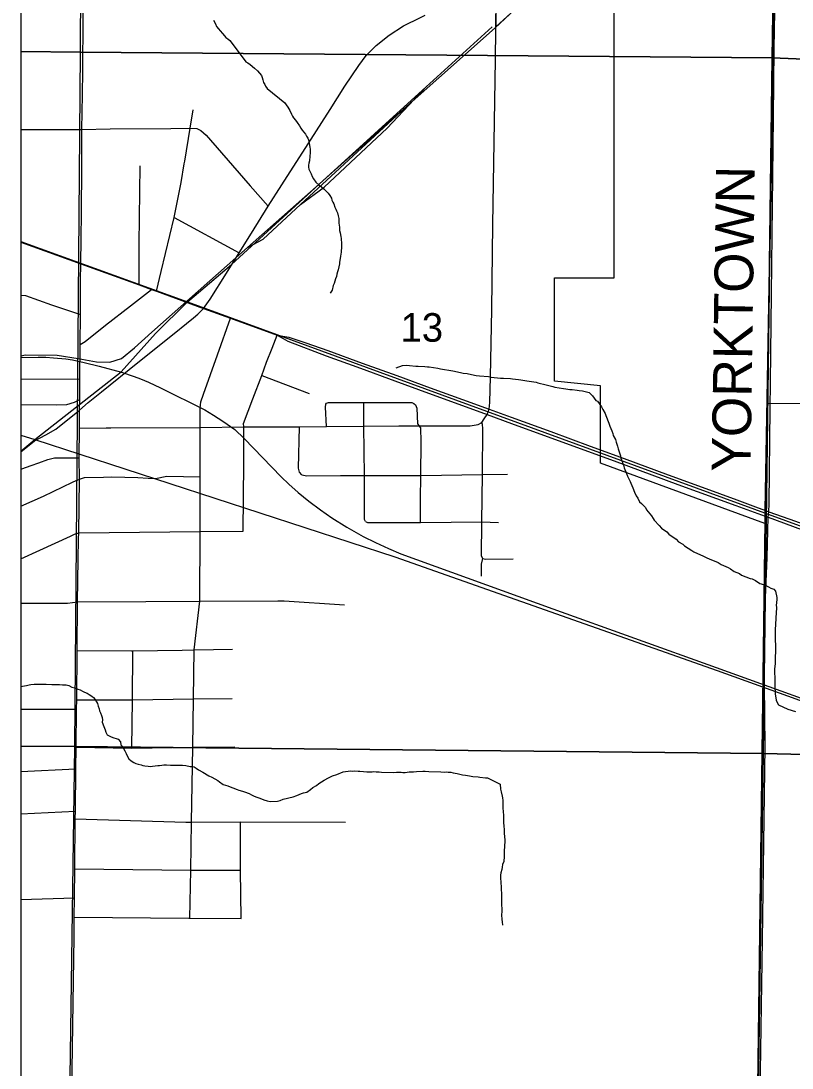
# Model space of a CAD drawing. Extents: x 0 to 34, y 0 to 22.
# Drawn here: x 2.1 to 3.229, y 16.762 to 18.295 of the extents above; entities that cross this region are included whole.
import ezdxf

# ---------------------------------------------------------------- set-up
doc = ezdxf.new("R2010")
doc.units = 0
for name, color, linetype in [('Default', 7, 'Continuous'), ('GM_X_City_Street', 7, 'Continuous'), ('GM_X_County_Road', 7, 'Continuous'), ('GM_X_Minor_River', 7, 'Continuous'), ('GM_X_Rail_Line', 7, 'Continuous'), ('GM_X_Section', 7, 'Continuous'), ('GM_X_Section_Text', 7, 'Continuous'), ('GM_X_State_Route', 7, 'Continuous'), ('GM_X_Township_Road', 7, 'Continuous'), ('GM_X_Township_Road_Text', 7, 'Continuous'), ('GM_X_US_Route', 7, 'Continuous'), ('SH_Cut_Line', 7, 'Continuous'), ('SH_Data', 7, 'Continuous')]:
    doc.layers.add(name, color=color, linetype=linetype)

msp = doc.modelspace()

# ---------------------------------------------------------------- linework, layer by layer
at = {"layer": 'Default'}
for points in [[(2.1, 19.2367), (2.1, 18.2496), (2.187, 18.2488), (2.1921, 19.2365)], [(2.1, 18.2496), (2.1, 17.2332), (2.1787, 17.2327), (2.187, 18.2488)], [(2.1, 17.2332), (2.1, 16.2301), (2.1648, 16.2299), (2.1787, 17.2327)]]:
    msp.add_lwpolyline(points, close=True, dxfattribs=at)
msp.add_lwpolyline([(3.4447, 17.732), (3.1921, 17.7348), (3.1889, 17.5591), (2.9487, 17.6473), (2.9487, 17.7603), (2.881, 17.7674), (2.881, 17.9186), (2.9686, 17.9186), (2.9685, 18.3256), (2.8381, 18.3256), (2.7959, 18.2862), (2.7959, 18.3665), (2.6903, 18.3173), (2.6935, 18.5959), (2.1906, 18.5508), (2.1906, 18.476), (2.1, 18.4765), (2.1, 16.2268)], dxfattribs=at)
at = {"layer": 'GM_X_City_Street'}
for p, q in [((2.3241, 18.0068), (2.4193, 17.9549)), ((2.4526, 17.7755), (2.5222, 17.7491)), ((2.1855, 17.6987), (2.2248, 17.6988)), ((2.6848, 17.5604), (2.685, 17.5782)), ((2.382, 17.3745), (2.4097, 17.375)), ((2.1, 17.2872), (2.1813, 17.287)), ((2.1, 17.196), (2.1803, 17.2)), ((2.1, 17.134), (2.1799, 17.1378)), ((2.1, 17.0089), (2.1783, 17.0109)), ((2.3475, 16.9811), (2.4222, 16.981))]:
    msp.add_line(p, q, dxfattribs=at)
for points in [[(2.7826, 17.7187), (2.7853, 17.7263), (2.7866, 17.736), (2.7876, 17.7736), (2.7892, 17.8722), (2.791, 17.9966), (2.7929, 18.1171), (2.7948, 18.2377), (2.7957, 18.3272), (2.7948, 18.3493)], [(2.3392, 18.0855), (2.3399, 18.0895), (2.3477, 18.1374), (2.352, 18.1646)], [(2.1, 18.1358), (2.1894, 18.1357), (2.2304, 18.1368), (2.3194, 18.1371), (2.3477, 18.1374), (2.3575, 18.1369), (2.3632, 18.1344), (2.3711, 18.1273), (2.4096, 18.0828), (2.4354, 18.0533), (2.4622, 18.0233)], [(2.2985, 17.899), (2.3055, 17.9279), (2.3241, 18.0068), (2.3344, 18.058), (2.3392, 18.0855)], [(2.2729, 17.9084), (2.2729, 17.9682), (2.2747, 18.0826)], [(2.1865, 17.8212), (2.1942, 17.8255), (2.2239, 17.8491), (2.2604, 17.8778), (2.2913, 17.9016)], [(2.1, 17.8931), (2.1065, 17.8925), (2.1448, 17.8791), (2.187, 17.8651)], [(2.3475, 16.9811), (2.3486, 17.0514), (2.3498, 17.122), (2.3515, 17.2314), (2.3527, 17.3022), (2.3538, 17.374), (2.3617, 17.4451), (2.3624, 17.5473), (2.3623, 17.6273), (2.3624, 17.6997), (2.3623, 17.7272), (2.3632, 17.737), (2.3671, 17.7481), (2.3876, 17.8059), (2.4066, 17.8594)], [(2.4252, 17.5479), (2.4262, 17.6466), (2.4262, 17.7003), (2.426, 17.7053), (2.4395, 17.7413), (2.4526, 17.7755), (2.4597, 17.7952), (2.4677, 17.8158), (2.4751, 17.8345)], [(2.1, 17.733), (2.1514, 17.7327), (2.1672, 17.7333), (2.1785, 17.7366), (2.1861, 17.7404)], [(2.5474, 17.701), (2.5459, 17.7294), (2.5463, 17.7334), (2.5472, 17.7353), (2.5502, 17.7361), (2.6021, 17.7363), (2.6355, 17.7363), (2.6723, 17.7363), (2.6754, 17.7348), (2.6778, 17.7327), (2.6794, 17.728), (2.6808, 17.705), (2.6828, 17.7019)], [(2.6047, 17.5621), (2.6032, 17.5647), (2.6029, 17.6294), (2.6022, 17.7012), (2.6021, 17.7363)], [(2.2248, 17.6988), (2.2317, 17.6988), (2.3624, 17.6997), (2.4262, 17.7003), (2.5079, 17.7005), (2.5474, 17.701), (2.6022, 17.7012), (2.6531, 17.7017), (2.6828, 17.7019), (2.7578, 17.7021), (2.7696, 17.7038), (2.7746, 17.7067), (2.7783, 17.7122), (2.7826, 17.7187)], [(2.685, 17.5782), (2.6852, 17.5942), (2.6854, 17.6294), (2.6859, 17.6785), (2.6854, 17.6991), (2.6828, 17.7019)], [(2.7744, 17.4819), (2.7742, 17.4995), (2.7762, 17.5078), (2.7744, 17.5111), (2.7746, 17.5614), (2.7757, 17.6305), (2.7764, 17.6979), (2.776, 17.7038), (2.7746, 17.7067)], [(2.5114, 17.6302), (2.5078, 17.634), (2.5065, 17.6399), (2.5079, 17.7005)], [(2.1, 17.6387), (2.1014, 17.6392), (2.1148, 17.6441), (2.126, 17.6478), (2.1393, 17.6526), (2.149, 17.6549), (2.1854, 17.6553)], [(2.181, 17.6221), (2.1855, 17.6241), (2.193, 17.6264), (2.2209, 17.6269)], [(2.2209, 17.6269), (2.2329, 17.6272), (2.271, 17.6265), (2.2862, 17.6251), (2.2972, 17.6247), (2.3134, 17.6285), (2.3623, 17.6273)], [(2.5114, 17.6302), (2.5185, 17.6286), (2.5678, 17.6292), (2.6029, 17.6294), (2.6854, 17.6294), (2.7757, 17.6305), (2.8126, 17.6313)], [(2.1, 17.5842), (2.1328, 17.5992), (2.1756, 17.6196), (2.181, 17.6221)], [(2.6047, 17.5621), (2.6074, 17.5604), (2.6848, 17.5604), (2.7746, 17.5614), (2.7991, 17.5606)], [(2.1, 17.5074), (2.1276, 17.52), (2.1726, 17.5406), (2.1782, 17.5432), (2.1846, 17.5453), (2.3624, 17.5473), (2.4252, 17.5479)], [(2.7762, 17.5078), (2.7795, 17.5068), (2.8209, 17.5072)], [(2.1, 17.4422), (2.1683, 17.4424), (2.1829, 17.4441), (2.283, 17.4449), (2.3617, 17.4451), (2.4759, 17.4457)], [(2.4759, 17.4457), (2.4856, 17.4458), (2.5737, 17.4398)], [(2.1825, 17.3732), (2.2621, 17.3724), (2.2639, 17.3724), (2.3359, 17.3737), (2.3538, 17.374), (2.382, 17.3745)], [(2.2626, 17.2302), (2.2633, 17.301), (2.2639, 17.3724)], [(2.1816, 17.301), (2.2633, 17.301), (2.3527, 17.3022), (2.4094, 17.303)], [(2.181, 17.2315), (2.2626, 17.2302), (2.3515, 17.2314), (2.3594, 17.2315), (2.4131, 17.2323)], [(2.1796, 17.1266), (2.3413, 17.122), (2.3498, 17.122), (2.4213, 17.1222), (2.5751, 17.1217)], [(2.4222, 16.981), (2.4213, 17.0514), (2.4213, 17.1222)], [(2.1791, 17.0536), (2.3486, 17.0514), (2.4213, 17.0514)], [(2.178, 16.9829), (2.3456, 16.9811), (2.3475, 16.9811)]]:
    msp.add_lwpolyline(points, dxfattribs=at)
at = {"layer": 'GM_X_County_Road'}
msp.add_line((2.1862, 17.7704), (2.1, 17.7699), dxfattribs=at)
msp.add_lwpolyline([(2.1, 17.664), (2.12, 17.68), (2.1366, 17.6889), (2.151, 17.6972), (2.1859, 17.7251)], dxfattribs=at)
at = {"layer": 'GM_X_Minor_River'}
for points in [[(2.3819, 18.2956), (2.385, 18.2903), (2.3862, 18.2865), (2.3892, 18.2831), (2.3919, 18.28), (2.395, 18.2763), (2.398, 18.2729), (2.3999, 18.2702), (2.403, 18.2683), (2.4056, 18.2657), (2.4266, 18.2381), (2.4293, 18.2346), (2.432, 18.2331), (2.4354, 18.2309), (2.4419, 18.2256), (2.4465, 18.2214), (2.4522, 18.2146), (2.4533, 18.2116), (2.4541, 18.2082), (2.4553, 18.2044), (2.4572, 18.2017), (2.4583, 18.1991), (2.4603, 18.1957), (2.4866, 18.1745), (2.4885, 18.1719), (2.4908, 18.1685), (2.4938, 18.1635), (2.4961, 18.1582), (2.4977, 18.1552), (2.4992, 18.1526), (2.5019, 18.1495), (2.5045, 18.1461), (2.5076, 18.1412), (2.5099, 18.1374), (2.5118, 18.1348), (2.5164, 18.1287), (2.5183, 18.1261), (2.5198, 18.123), (2.521, 18.1204), (2.5222, 18.1151), (2.5229, 18.1098), (2.5233, 18.1067), (2.5234, 18.1014), (2.523, 18.0968), (2.5223, 18.09), (2.5215, 18.0866), (2.5208, 18.0835), (2.5212, 18.0805), (2.5216, 18.0778), (2.525, 18.0706), (2.5266, 18.0669), (2.5281, 18.0634), (2.5319, 18.0585), (2.5365, 18.054), (2.5399, 18.0517), (2.5434, 18.0487), (2.5464, 18.0461), (2.5498, 18.0423), (2.5521, 18.0389), (2.5548, 18.0351), (2.5552, 18.0324), (2.5567, 18.0294), (2.5583, 18.0267), (2.5594, 18.0222), (2.561, 18.0192), (2.5621, 18.0165), (2.5633, 18.0135), (2.5644, 18.0093), (2.5656, 18.0055), (2.5656, 17.9987), (2.5664, 17.9926), (2.5664, 17.988)], [(2.5664, 17.988), (2.5672, 17.9842), (2.5684, 17.9789), (2.5688, 17.9763), (2.5688, 17.9736), (2.5692, 17.9706), (2.5692, 17.9615), (2.5689, 17.9588), (2.5689, 17.9561), (2.5678, 17.9504), (2.5674, 17.947), (2.5663, 17.9417), (2.5663, 17.939), (2.5652, 17.9345), (2.5644, 17.9303), (2.5637, 17.9273), (2.5626, 17.9238), (2.5618, 17.9204), (2.5607, 17.917), (2.5585, 17.9101), (2.5573, 17.9071), (2.5559, 17.9003), (2.5528, 17.8961)], [(2.6494, 17.7867), (2.6585, 17.7902), (2.6642, 17.7906), (2.6691, 17.7903), (2.6783, 17.7895), (2.6817, 17.7892), (2.6915, 17.7888), (2.695, 17.7885), (2.6976, 17.7881), (2.7102, 17.7863), (2.7143, 17.7855), (2.717, 17.7848), (2.7292, 17.783), (2.7322, 17.7822), (2.7436, 17.78), (2.7474, 17.7792), (2.7531, 17.7785), (2.7596, 17.777), (2.7664, 17.7755), (2.7713, 17.7752), (2.7846, 17.7741), (2.7884, 17.7734), (2.8021, 17.7719), (2.8067, 17.7715), (2.8169, 17.7712), (2.8199, 17.7705), (2.8283, 17.7698), (2.8317, 17.7694), (2.8405, 17.7679), (2.8442, 17.7672), (2.8541, 17.7657), (2.8568, 17.7649), (2.869, 17.762), (2.8785, 17.7597), (2.8819, 17.7586), (2.8944, 17.7568), (2.8978, 17.756), (2.9035, 17.7553), (2.9069, 17.7549), (2.9145, 17.7542), (2.9172, 17.7538), (2.9221, 17.7531), (2.9263, 17.7524), (2.932, 17.7509), (2.9366, 17.746), (2.9416, 17.7391), (2.9442, 17.738), (2.95, 17.7297), (2.9519, 17.7259), (2.9553, 17.7198), (2.9561, 17.7172), (2.9607, 17.7058), (2.9622, 17.7016), (2.9653, 17.6944), (2.9665, 17.6906), (2.9673, 17.6876), (2.9703, 17.6819), (2.9715, 17.6778), (2.9734, 17.6721), (2.9742, 17.6683), (2.9777, 17.658), (2.9784, 17.6546), (2.9823, 17.6444), (2.9834, 17.6406), (2.9865, 17.6322), (2.988, 17.6285), (2.9919, 17.6205), (2.993, 17.6178), (2.9946, 17.6144), (2.9957, 17.6114), (2.9984, 17.605), (3.0007, 17.5993), (3.0034, 17.5959), (3.0057, 17.5909), (3.0087, 17.5883), (3.0145, 17.5822), (3.016, 17.5792), (3.0233, 17.5701), (3.0256, 17.5663), (3.0271, 17.5637), (3.0343, 17.5561), (3.0378, 17.5523), (3.0454, 17.5467), (3.0488, 17.5433), (3.0591, 17.5361), (3.0625, 17.5323), (3.069, 17.5286), (3.0717, 17.5263), (3.0823, 17.5195), (3.0854, 17.5176), (3.0995, 17.5112), (3.1044, 17.5086), (3.1075, 17.5071), (3.1208, 17.5018), (3.1253, 17.4992), (3.1352, 17.4947), (3.139, 17.4928), (3.144, 17.4887), (3.152, 17.486), (3.155, 17.4834), (3.1676, 17.4785)], [(3.1676, 17.4785), (3.1706, 17.4778), (3.1756, 17.4755), (3.182, 17.471), (3.1874, 17.4695), (3.1946, 17.4665), (3.198, 17.4642), (3.2022, 17.4631), (3.2049, 17.4601), (3.2068, 17.4506), (3.2065, 17.4476), (3.2057, 17.4392), (3.2061, 17.4365), (3.2058, 17.4274), (3.2051, 17.4221), (3.2051, 17.4183), (3.2047, 17.413), (3.2044, 17.402), (3.2044, 17.3993), (3.2046, 17.3697), (3.2042, 17.3655), (3.2043, 17.3537), (3.2035, 17.3465), (3.2036, 17.3279), (3.204, 17.3214), (3.2041, 17.3093), (3.2045, 17.3066), (3.2057, 17.3006), (3.2072, 17.2971), (3.2091, 17.2937), (3.2228, 17.2873), (3.2338, 17.2836)], [(2.1, 17.3206), (2.1022, 17.321), (2.1052, 17.3214), (2.1082, 17.3221), (2.112, 17.3228), (2.1147, 17.3232), (2.1196, 17.3239), (2.1371, 17.3238), (2.145, 17.3233), (2.1564, 17.3232), (2.161, 17.3228), (2.1663, 17.3227), (2.17, 17.322), (2.1746, 17.3196), (2.1787, 17.3185), (2.1833, 17.3165), (2.1867, 17.3153), (2.1901, 17.3138), (2.1931, 17.3123), (2.1969, 17.3107), (2.1999, 17.3088), (2.2037, 17.3065), (2.2063, 17.3045), (2.2086, 17.3015), (2.2104, 17.2981), (2.2119, 17.2954), (2.213, 17.2916), (2.2145, 17.2878), (2.2152, 17.2847), (2.2164, 17.2821), (2.2178, 17.2779), (2.219, 17.2752), (2.2193, 17.2714), (2.2189, 17.268)], [(2.2189, 17.268), (2.2215, 17.2619), (2.2233, 17.2569), (2.2245, 17.2535), (2.2263, 17.2497), (2.229, 17.2482), (2.232, 17.2466), (2.2361, 17.2451), (2.2396, 17.2443), (2.2422, 17.2435), (2.2456, 17.2393), (2.2463, 17.2351), (2.2489, 17.2324), (2.2523, 17.2263), (2.2542, 17.2225), (2.256, 17.2179), (2.2579, 17.2145), (2.2616, 17.2114), (2.2654, 17.2091), (2.2684, 17.2079), (2.2718, 17.2068), (2.276, 17.2056), (2.2787, 17.2048), (2.2813, 17.2044), (2.2862, 17.2036), (2.2893, 17.2032), (2.2927, 17.2036), (2.2965, 17.2043), (2.3003, 17.2046), (2.3029, 17.2046), (2.3063, 17.2053), (2.309, 17.2057), (2.3132, 17.2057), (2.3189, 17.2052), (2.3223, 17.2052), (2.3329, 17.2055), (2.3367, 17.2054), (2.3416, 17.2046), (2.348, 17.2034), (2.3507, 17.2034), (2.3537, 17.2026), (2.3567, 17.2007), (2.3601, 17.1984), (2.3662, 17.1949), (2.3752, 17.1899), (2.3794, 17.1876), (2.3839, 17.1853), (2.3881, 17.1826), (2.3907, 17.1807), (2.396, 17.1772), (2.4028, 17.1752), (2.4062, 17.1737), (2.4104, 17.1721), (2.4164, 17.1698), (2.4191, 17.1686), (2.4243, 17.1671), (2.4274, 17.1663), (2.4342, 17.164), (2.4376, 17.1617), (2.4414, 17.1597), (2.4455, 17.1582), (2.4497, 17.157), (2.4557, 17.1547), (2.4606, 17.1531), (2.4648, 17.1523), (2.4754, 17.1526), (2.4796, 17.1537), (2.4838, 17.1555), (2.4986, 17.1588), (2.5039, 17.1607), (2.5108, 17.1637), (2.5138, 17.1648), (2.5184, 17.1659), (2.5237, 17.1696), (2.5275, 17.1726), (2.5325, 17.1756), (2.5363, 17.1782), (2.5439, 17.1831), (2.5504, 17.1865), (2.5561, 17.1895), (2.5626, 17.1917), (2.5717, 17.1954), (2.5824, 17.1968), (2.585, 17.1964), (2.588, 17.1968), (2.5937, 17.1963), (2.5964, 17.1963), (2.6013, 17.1959), (2.6066, 17.1955), (2.6142, 17.1954), (2.6169, 17.1958), (2.6203, 17.1957), (2.6244, 17.1953), (2.6278, 17.1949), (2.6461, 17.1947), (2.6498, 17.1951), (2.654, 17.195), (2.6567, 17.195), (2.6593, 17.1946), (2.6627, 17.1946), (2.6684, 17.1953)], [(2.6684, 17.1953), (2.6749, 17.1956), (2.6791, 17.196), (2.6882, 17.1966), (2.692, 17.1966), (2.6973, 17.1958), (2.7147, 17.1956), (2.7196, 17.1952), (2.723, 17.1956), (2.7257, 17.1952), (2.7295, 17.1948), (2.7329, 17.194), (2.7355, 17.1936), (2.7386, 17.1932), (2.7424, 17.192), (2.7465, 17.1912), (2.7511, 17.1904), (2.7567, 17.1896), (2.7617, 17.1888), (2.7692, 17.188), (2.7719, 17.1876), (2.7802, 17.1867), (2.7829, 17.1867), (2.8014, 17.1774), (2.8021, 17.1702), (2.8032, 17.1664), (2.8047, 17.1599), (2.805, 17.1573), (2.8057, 17.1538), (2.8057, 17.1504), (2.8053, 17.147), (2.8056, 17.1421), (2.806, 17.1375), (2.8063, 17.1314), (2.8066, 17.1242), (2.8066, 17.1212), (2.8069, 17.1159), (2.8077, 17.1113), (2.8076, 17.1056), (2.8083, 17.0957), (2.8082, 17.0851), (2.8074, 17.0809), (2.8073, 17.0714), (2.8069, 17.0642), (2.805, 17.0597), (2.8045, 17.0559), (2.8041, 17.0525), (2.8026, 17.0479), (2.8022, 17.0445), (2.8021, 17.04), (2.8025, 17.0339), (2.8032, 17.0263), (2.8031, 17.0217), (2.8035, 17.0187), (2.8038, 17.0145), (2.8038, 17.0092), (2.8037, 16.9997), (2.804, 16.9959), (2.804, 16.991), (2.8036, 16.9861), (2.8043, 16.9796), (2.8046, 16.9758), (2.805, 16.9712)]]:
    msp.add_lwpolyline(points, dxfattribs=at)
at = {"layer": 'GM_X_Rail_Line'}
for p, q in [((2.6932, 18.1982), (2.7899, 18.2861)), ((2.6759, 18.1794), (2.6932, 18.1982)), ((2.5094, 18.0258), (2.6759, 18.1794)), ((2.1, 17.9715), (2.3438, 17.8832)), ((2.1205, 17.682), (2.2468, 17.781)), ((2.1, 17.6882), (2.1205, 17.682)), ((2.1, 17.665), (2.1205, 17.682))]:
    msp.add_line(p, q, dxfattribs=at)
for points in [[(2.3438, 17.8832), (2.4082, 17.9379), (2.5423, 18.061), (2.7943, 18.2844), (3.1322, 18.5996), (3.3125, 18.7514), (3.4225, 18.8451), (3.8301, 19.2157), (4.2487, 19.5941), (4.47, 19.794), (4.5566, 19.8598), (4.6465, 19.9302), (4.7011, 19.9679), (5.2057, 20.3431), (5.7213, 20.7403), (5.9437, 20.9)], [(2.4317, 17.9628), (2.5365, 18.0557), (2.6932, 18.1982)], [(2.5094, 18.0258), (2.544, 18.0513), (2.636, 18.1374), (2.6759, 18.1794)], [(2.4317, 17.9628), (2.4545, 17.975), (2.5094, 18.0258)], [(2.1, 17.8046), (2.1069, 17.8058), (2.1529, 17.8053), (2.1839, 17.8005), (2.2104, 17.7954), (2.2302, 17.7953), (2.2473, 17.8005), (2.2665, 17.8161), (2.2917, 17.8388), (2.4317, 17.9628)], [(2.2468, 17.781), (2.2969, 17.837), (2.3438, 17.8832)], [(2.3438, 17.8832), (3.2394, 17.556), (3.7037, 17.3885), (4.1527, 17.2251), (5.0251, 16.9129), (5.72, 16.6602), (6.7111, 16.2981), (7.2308, 16.1113), (7.9999, 15.8344), (8.5456, 15.6361), (8.9, 15.5035)], [(2.1, 17.8021), (2.125, 17.8022), (2.1365, 17.8022), (2.1478, 17.8016), (2.1656, 17.8001), (2.1756, 17.7983), (2.1924, 17.7948), (2.2144, 17.7895), (2.247, 17.7804), (2.2659, 17.7743), (2.2749, 17.7709), (2.2867, 17.766), (2.3044, 17.7574), (2.369, 17.7253), (2.382, 17.7174), (2.3957, 17.7086), (2.413, 17.6964), (2.427, 17.6833), (2.4808, 17.6272), (2.4923, 17.6165), (2.5058, 17.6045), (2.5217, 17.5919), (2.5384, 17.5792), (2.5553, 17.5672), (2.5769, 17.5537), (2.6009, 17.5401), (2.6191, 17.531), (2.6381, 17.5223), (2.656, 17.5146), (2.8786, 17.4343), (3.1179, 17.348), (3.3371, 17.269)], [(2.1205, 17.682), (2.6475, 17.5103), (3.1194, 17.3438), (3.8981, 17.0634), (4.4129, 16.8774), (5.5123, 16.484), (6.2938, 16.2008), (7.1773, 15.8785), (7.9469, 15.6046), (8.6994, 15.3378), (8.9, 15.264)]]:
    msp.add_lwpolyline(points, dxfattribs=at)
at = {"layer": 'GM_X_Section'}
for points in [[(2.1921, 19.2365), (3.2151, 19.2391), (3.2, 18.2405), (2.187, 18.2488)], [(3.2151, 19.2391), (4.2026, 19.2018), (4.1997, 18.1993), (3.2, 18.2405)], [(3.2, 18.2405), (3.1868, 17.2222), (2.1787, 17.2327), (2.187, 18.2488)], [(4.1997, 18.1993), (4.1831, 17.1984), (3.1868, 17.2222), (3.2, 18.2405)], [(3.1868, 17.2222), (3.1722, 16.2262), (2.1648, 16.2299), (2.1787, 17.2327)], [(3.1868, 17.2222), (4.1831, 17.1984), (4.1651, 16.2036), (3.1722, 16.2262)]]:
    msp.add_lwpolyline(points, close=True, dxfattribs=at)
at = {"layer": 'GM_X_State_Route'}
for points in [[(2.1907, 18.2395), (2.1909, 18.2796), (2.1915, 18.355), (2.1918, 18.4146), (2.1921, 18.4794), (2.1921, 18.4896)], [(2.3675, 17.8737), (2.3772, 17.8874), (2.4011, 17.9255), (2.4193, 17.9549), (2.4377, 17.9837), (2.4622, 18.0233), (2.4822, 18.0546), (2.5203, 18.1147), (2.5525, 18.1647), (2.5743, 18.199), (2.5949, 18.2292), (2.6056, 18.2439), (2.6203, 18.2587), (2.6389, 18.2738), (2.6603, 18.2875), (2.6848, 18.2997), (2.6919, 18.303)], [(2.1879, 17.9388), (2.1883, 17.9754), (2.1889, 18.0136), (2.1892, 18.0806), (2.1894, 18.1357), (2.1903, 18.1865), (2.1906, 18.2215), (2.1907, 18.2395)], [(2.1859, 17.7251), (2.1861, 17.7404), (2.1862, 17.7704), (2.1865, 17.8212), (2.187, 17.8651), (2.1874, 17.9144), (2.1879, 17.9388)], [(2.3526, 17.8602), (2.3589, 17.8653), (2.3675, 17.8737)], [(2.1859, 17.7251), (2.1984, 17.7361), (2.2181, 17.7519), (2.2711, 17.7944), (2.3242, 17.8373), (2.3423, 17.8519), (2.3526, 17.8602)], [(2.1844, 17.5363), (2.1846, 17.5453), (2.1855, 17.6241), (2.1854, 17.6553), (2.1855, 17.6987), (2.1859, 17.7251)], [(2.1796, 17.1276), (2.1799, 17.1378), (2.1803, 17.2), (2.181, 17.2315), (2.1813, 17.287), (2.1816, 17.301), (2.1825, 17.3732), (2.1829, 17.4441), (2.1836, 17.5063), (2.1844, 17.5363)], [(2.1659, 16.3414), (2.1675, 16.3795), (2.1709, 16.5269), (2.1739, 16.694), (2.1758, 16.8248), (2.1778, 16.954), (2.178, 16.9829), (2.1783, 17.0109), (2.1791, 17.0536), (2.1796, 17.1266), (2.1796, 17.1276)]]:
    msp.add_lwpolyline(points, dxfattribs=at)
at = {"layer": 'GM_X_Township_Road'}
msp.add_line((3.1942, 17.5683), (3.1952, 17.5762), dxfattribs=at)
for points in [[(3.1491, 14.2171), (3.1576, 14.794), (3.1628, 15.2158), (3.1774, 16.6199), (3.1774, 16.6219), (3.1894, 17.563), (3.1895, 17.5705), (3.1896, 17.5787), (3.2069, 18.535), (3.2116, 19.2346), (3.2118, 19.2455), (3.2241, 20.2443), (2.209, 20.2314), (2.1, 20.2296), (2.1, 14.2219)], [(8.9, 14.1483), (8.9, 20.2053), (7.2271, 20.2132), (6.4763, 20.2191), (6.0936, 20.222), (5.2207, 20.2288), (4.224, 20.2365), (3.2241, 20.2443), (3.2118, 19.2455), (3.2116, 19.2346), (3.2069, 18.535), (3.1896, 17.5787), (3.1895, 17.5705), (3.1894, 17.563), (3.1774, 16.6219), (3.1774, 16.6199), (3.1628, 15.2158), (3.1576, 14.794), (3.1491, 14.2171)], [(3.1968, 17.7272), (3.1972, 17.7655), (3.2017, 18.1538), (3.2027, 18.2535), (3.2066, 18.4741), (3.2071, 18.5344)], [(3.1952, 17.5762), (3.1953, 17.5878), (3.1968, 17.7272)], [(3.1825, 16.7248), (3.1856, 16.949), (3.1895, 17.2331), (3.1886, 17.3226), (3.1881, 17.4029), (3.1894, 17.4385), (3.1927, 17.509), (3.1936, 17.5489), (3.1942, 17.5683)]]:
    msp.add_lwpolyline(points, dxfattribs=at)
at = {"layer": 'GM_X_US_Route'}
msp.add_line((2.1, 17.9708), (2.1879, 17.9388), dxfattribs=at)
for points in [[(2.1879, 17.9388), (2.2729, 17.9084), (2.2913, 17.9016), (2.2985, 17.899), (2.3675, 17.8737)], [(2.3675, 17.8737), (2.4066, 17.8594), (2.4751, 17.8345), (2.4837, 17.8296)], [(2.4751, 17.8345), (2.4922, 17.8318), (2.5172, 17.8234), (2.5494, 17.812), (2.5997, 17.7937), (2.6501, 17.7754), (2.6993, 17.7575), (2.7465, 17.7403), (2.7853, 17.7263)], [(2.4837, 17.8296), (2.4907, 17.8257), (2.5468, 17.8044), (2.597, 17.7861), (2.6474, 17.7678), (2.6966, 17.7498), (2.7465, 17.7317), (2.7826, 17.7187), (2.8183, 17.7055), (2.8971, 17.6767), (2.9684, 17.6505), (3.0618, 17.6163), (3.1469, 17.5853), (3.1898, 17.5699), (3.1942, 17.5683), (3.2693, 17.5404), (3.3689, 17.5042), (3.4197, 17.4856)], [(2.7853, 17.7263), (2.8179, 17.7145), (2.8756, 17.6934), (2.9332, 17.6724), (2.9833, 17.6539), (3.0477, 17.6303), (3.0975, 17.612), (3.1481, 17.5935), (3.1755, 17.5836), (3.1899, 17.5782), (3.1952, 17.5762)], [(3.1952, 17.5762), (3.2341, 17.5622), (3.2778, 17.5462), (3.3196, 17.5309), (3.3697, 17.5125), (3.4101, 17.4978), (3.4458, 17.4849)]]:
    msp.add_lwpolyline(points, dxfattribs=at)
at = {"layer": 'SH_Cut_Line'}
msp.add_lwpolyline([(8.9, 14.1483), (8.9, 20.9), (2.1, 20.9), (2.1, 14.2219)], dxfattribs=at)
at = {"layer": 'SH_Data'}
msp.add_line((2.1, 20.9), (2.1, 14.1), dxfattribs=at)

# ---------------------------------------------------------------- texts
at = {"layer": 'GM_X_Section_Text'}
msp.add_text('13', height=0.04186, rotation=0, dxfattribs=at).set_placement((2.6558, 17.825))
at = {"layer": 'GM_X_Township_Road_Text'}
msp.add_text('YORKTOWN', height=0.05682, rotation=89.1748, dxfattribs=at).set_placement((3.1681, 17.6344))

doc.saveas('drawing.dxf')
